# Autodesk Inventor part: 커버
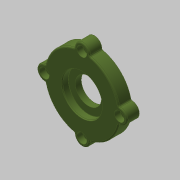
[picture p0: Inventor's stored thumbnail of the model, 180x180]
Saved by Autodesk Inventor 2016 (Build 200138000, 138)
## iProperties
Created: 2016-06
Part Number: 커버
Material: 알루미늄 6061
Document SubType Name: Modeling
Designer: mduedu
Density: 2.71 g/cm^3
Appearance: 올리브 녹색
Author: mduedu
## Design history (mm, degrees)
sketch "스케치1"
  geometry: C1 r 30 at (0, 0); 1 further point
  constraints: 1 centre point, 1 coincident
  dimensions: "d0" = 60 diameter of C1
extrude "돌출1" new body sketch "스케치1" distance "d2" = 10; taper "d3" = 0 deg
sketch "스케치5"
  geometry: C1 r 6 at (0, 30); 2 further points
  constraints: 2 vertical alignment, 1 centre point, 1 other
  dimensions: "d61" = 12 diameter of C1
extrude "돌출3" join sketch "스케치5" stored distance "d62" = 10; taper "d63" = 0 deg
sketch "스케치2"
  geometry: C1 r 21 at (0, 0); 1 further point
  constraints: 1 centre point, 1 coincident
  dimensions: "d4" = 42 diameter of C1
extrude "돌출2" join sketch "스케치2" distance "d6" = 3; taper "d7" = 0 deg
hole "구멍1" diameter "d11" = 35; stored, may be unused: countersink angle "d15" = 90 deg, drill point angle "d17" = 0 deg; dims "d9" = 10, "d10" = 10, "d12" = 6, "d13" = 4, "d14" = 2, "d16" = 3
hole "구멍2" diameter "d20" = 32; stored, may be unused: countersink angle "d24" = 90 deg, drill point angle "d26" = 0 deg; dims "d21" = 6, "d22" = 4, "d23" = 2, "d25" = 5.2, "d67" = 10, "d68" = 10
hole "구멍3" diameter "d29" = 21; stored, may be unused: countersink angle "d33" = 90 deg, drill point angle "d35" = 0 deg; dims "d27" = 10, "d28" = 10, "d30" = 6, "d31" = 4, "d32" = 2, "d34" = 5
fillet "모깎기2" dims "d36" = 3
fillet "모깎기3" dims "d37" = 0.1
chamfer "모따기1" distance "d38" = 0.75; stored, may be unused: second distance "d39" = 2, angle "d40" = 30 deg
chamfer "모따기2" distance "d42" = 0.5; stored, may be unused: second distance "d43" = 2, angle "d44" = 30 deg
sketch "스케치6"
  geometry: A1 r 30 centre (0, 0) between (29.4, 5.97) and (5.97, 29.4) reference; 3 further points
  constraints: 2 vertical alignment, 1 coincident, 3 other
hole "구멍5" sketch "스케치6" at (0, 30) diameter "d69" = 4.5; stored, may be unused: countersink angle "d73" = 90 deg, drill point angle "d75" = 118 deg; dims "d70" = 6, "d71" = 8, "d72" = 4.6, "d74" = 8
fillet "모깎기5" dims "d79" = 1
fillet "모깎기6" dims "d80" = 1
node "솔리드1"
pattern_circular "원형 패턴1" dims angle "d65" = 360 deg
pattern_circular "원형 패턴2" dims angle "d77" = 360 deg
node "투영된 루프1"
